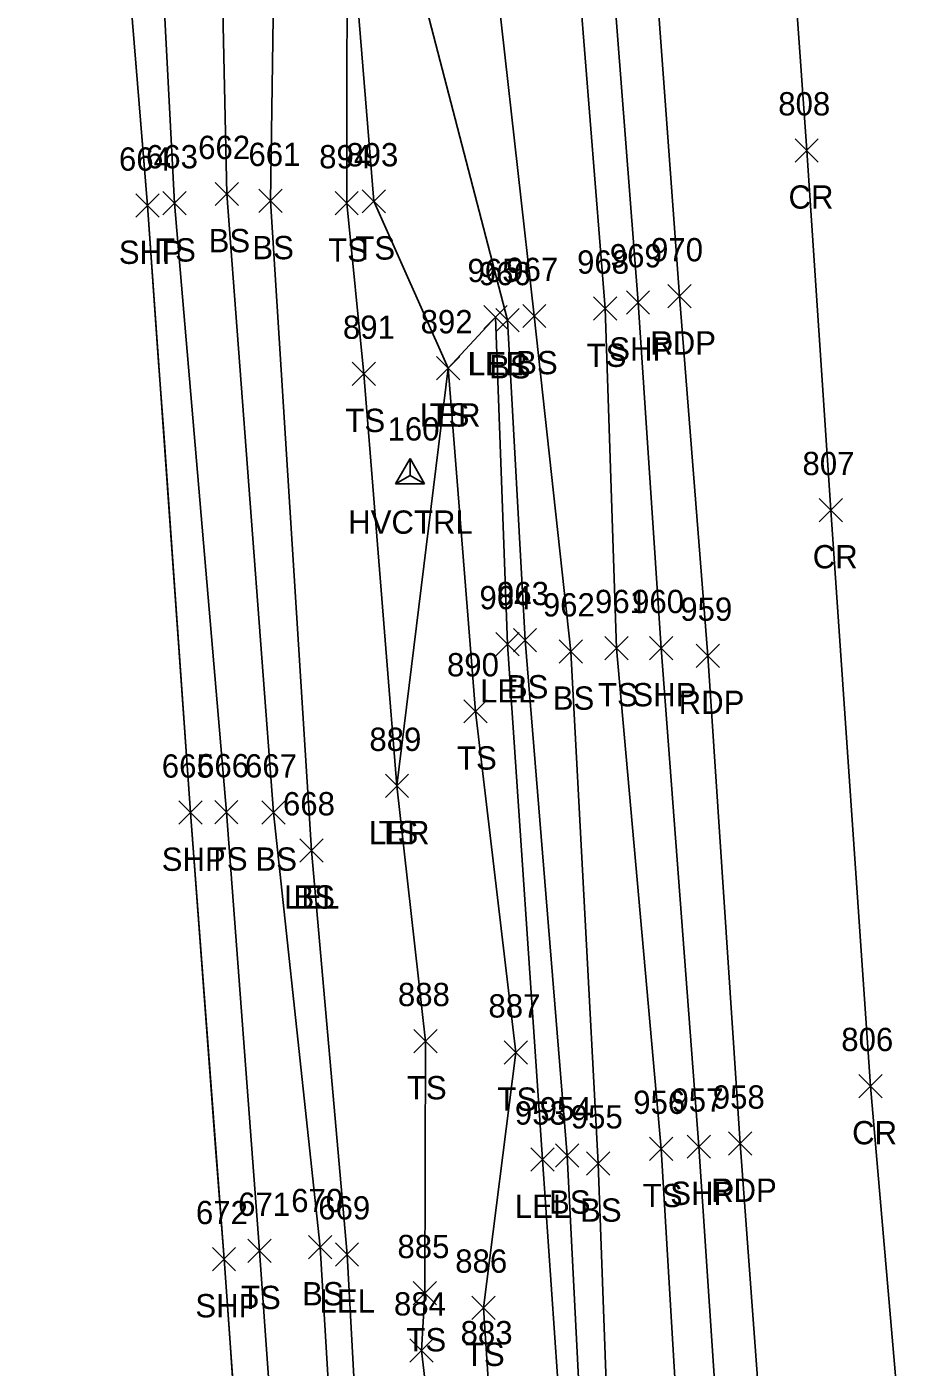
# Model space of a CAD drawing. Extents: x 1650221 to 1650634, y 244606 to 249996.
# Drawn here: x 1650345.8 to 1650421.8, y 245461.1 to 245576.1 of the extents above; entities that cross this region are included whole.
import ezdxf

# ---------------------------------------------------------------- set-up
doc = ezdxf.new("R2010")
doc.units = 0
for name, color, linetype in [('C_A', 7, 'Continuous'), ('C_I', 7, 'Continuous'), ('CPSM', 7, 'Continuous'), ('L_A', 7, 'Continuous'), ('L_I', 7, 'Continuous'), ('L_TIC', 7, 'Continuous'), ('LARO', 7, 'Continuous'), ('LELB', 7, 'Continuous'), ('LSOGP', 7, 'Continuous'), ('P_A', 7, 'Continuous'), ('P_I', 7, 'Continuous'), ('P_TIC', 7, 'Continuous'), ('PET', 7, 'Continuous'), ('PRC', 7, 'Continuous'), ('PSP', 7, 'Continuous')]:
    doc.layers.add(name, color=color, linetype=linetype)

msp = doc.modelspace()

# ---------------------------------------------------------------- linework, layer by layer
at = {"layer": 'CPSM'}
for p, q in [((1650377.43, 245536.88), (1650378.68, 245539.05)), ((1650379.93, 245536.88), (1650378.68, 245539.05)), ((1650378.68, 245537.6), (1650378.68, 245539.05)), ((1650377.43, 245536.88), (1650378.68, 245537.6)), ((1650378.68, 245537.6), (1650378.68, 245537.6)), ((1650378.68, 245537.6), (1650379.93, 245536.88)), ((1650377.43, 245536.88), (1650379.93, 245536.88))]:
    msp.add_line(p, q, dxfattribs=at)
at = {"layer": 'L_TIC'}
for points in [[(1650361.95, 245560.76), (1650363.95, 245562.76)], [(1650363.95, 245560.76), (1650361.95, 245562.76)], [(1650357.47, 245559.96), (1650359.47, 245561.96)], [(1650359.47, 245559.96), (1650357.47, 245561.96)], [(1650365.7, 245560.16), (1650367.7, 245562.16)], [(1650367.7, 245560.16), (1650365.7, 245562.16)], [(1650372.24, 245559.96), (1650374.24, 245561.96)], [(1650374.24, 245559.96), (1650372.24, 245561.96)], [(1650374.57, 245560.13), (1650376.57, 245562.13)], [(1650376.57, 245560.13), (1650374.57, 245562.13)], [(1650385.02, 245550.2), (1650387.02, 245552.2)], [(1650387.02, 245550.2), (1650385.02, 245552.2)], [(1650385.02, 245550.2), (1650387.02, 245552.2)], [(1650387.02, 245550.2), (1650385.02, 245552.2)], [(1650386.04, 245549.93), (1650388.04, 245551.93)], [(1650388.04, 245549.93), (1650386.04, 245551.93)], [(1650388.35, 245550.29), (1650390.35, 245552.29)], [(1650390.35, 245550.29), (1650388.35, 245552.29)], [(1650394.43, 245550.92), (1650396.43, 245552.92)], [(1650396.43, 245550.92), (1650394.43, 245552.92)], [(1650373.72, 245545.33), (1650375.72, 245547.33)], [(1650375.72, 245545.33), (1650373.72, 245547.33)], [(1650380.95, 245545.8), (1650382.95, 245547.8)], [(1650382.95, 245545.8), (1650380.95, 245547.8)], [(1650380.95, 245545.8), (1650382.95, 245547.8)], [(1650382.95, 245545.8), (1650380.95, 245547.8)], [(1650387.55, 245522.47), (1650389.55, 245524.47)], [(1650389.55, 245522.47), (1650387.55, 245524.47)], [(1650386.05, 245522.12), (1650388.05, 245524.12)], [(1650388.05, 245522.12), (1650386.05, 245524.12)], [(1650391.49, 245521.5), (1650393.49, 245523.5)], [(1650393.49, 245521.5), (1650391.49, 245523.5)], [(1650395.41, 245521.79), (1650397.41, 245523.79)], [(1650397.41, 245521.79), (1650395.41, 245523.79)], [(1650383.3, 245516.36), (1650385.3, 245518.36)], [(1650385.3, 245516.36), (1650383.3, 245518.36)], [(1650376.56, 245509.96), (1650378.56, 245511.96)], [(1650378.56, 245509.96), (1650376.56, 245511.96)], [(1650376.56, 245509.96), (1650378.56, 245511.96)], [(1650378.56, 245509.96), (1650376.56, 245511.96)], [(1650361.91, 245507.7), (1650363.91, 245509.7)], [(1650363.91, 245507.7), (1650361.91, 245509.7)], [(1650365.97, 245507.68), (1650367.97, 245509.68)], [(1650367.97, 245507.68), (1650365.97, 245509.68)], [(1650369.23, 245504.43), (1650371.23, 245506.43)], [(1650371.23, 245504.43), (1650369.23, 245506.43)], [(1650369.23, 245504.43), (1650371.23, 245506.43)], [(1650371.23, 245504.43), (1650369.23, 245506.43)], [(1650379, 245488.06), (1650381, 245490.06)], [(1650381, 245488.06), (1650379, 245490.06)], [(1650386.77, 245487.08), (1650388.77, 245489.08)], [(1650388.77, 245487.08), (1650386.77, 245489.08)], [(1650399.25, 245478.81), (1650401.25, 245480.81)], [(1650401.25, 245478.81), (1650399.25, 245480.81)], [(1650389.04, 245477.89), (1650391.04, 245479.89)], [(1650391.04, 245477.89), (1650389.04, 245479.89)], [(1650391.17, 245478.25), (1650393.17, 245480.25)], [(1650393.17, 245478.25), (1650391.17, 245480.25)], [(1650393.84, 245477.56), (1650395.84, 245479.56)], [(1650395.84, 245477.56), (1650393.84, 245479.56)], [(1650364.76, 245470.06), (1650366.76, 245472.06)], [(1650366.76, 245470.06), (1650364.76, 245472.06)], [(1650369.97, 245470.38), (1650371.97, 245472.38)], [(1650371.97, 245470.38), (1650369.97, 245472.38)], [(1650372.27, 245469.75), (1650374.27, 245471.75)], [(1650374.27, 245469.75), (1650372.27, 245471.75)], [(1650378.96, 245466.43), (1650380.96, 245468.43)], [(1650380.96, 245466.43), (1650378.96, 245468.43)], [(1650383.98, 245465.18), (1650385.98, 245467.18)], [(1650385.98, 245465.18), (1650383.98, 245467.18)], [(1650378.67, 245461.51), (1650380.67, 245463.51)], [(1650380.67, 245461.51), (1650378.67, 245463.51)]]:
    msp.add_lwpolyline(points, dxfattribs=at)
at = {"layer": 'LARO'}
for points in [[(1650377.56, 245510.96), (1650381.95, 245546.8), (1650386.02, 245551.2)], [(1650421.38, 244936.36), (1650423.35, 244936.27), (1650425.89, 244936.22), (1650434.3, 244938.37), (1650430.48, 244972), (1650427.02, 245018.52), (1650423.68, 245067.08), (1650420.77, 245123.48), (1650416.16, 245170.75), (1650416.29, 245170.75), (1650411.97, 245219.01), (1650407.36, 245272.17), (1650403.92, 245328.57), (1650398.22, 245379.76), (1650393.14, 245434.28), (1650390.04, 245478.89), (1650387.05, 245523.12), (1650386.02, 245551.2)], [(1650370.23, 245505.43), (1650373.27, 245470.75), (1650376.08, 245419.34), (1650380.61, 245367.82), (1650383.54, 245316.3), (1650388.29, 245270.51), (1650390.54, 245221.61), (1650394.38, 245168.62), (1650397.75, 245118.3), (1650404.08, 245063.51), (1650406.12, 245018.23), (1650409.93, 244966.8), (1650411.89, 244938.28)]]:
    msp.add_lwpolyline(points, dxfattribs=at)
at = {"layer": 'LELB'}
for points in [[(1650349.13, 245703.09), (1650351.39, 245660.59), (1650355.99, 245608.05), (1650358.47, 245560.96), (1650362.91, 245508.7), (1650365.76, 245471.06), (1650369.41, 245419.53), (1650373.04, 245367.18), (1650376.89, 245316.29), (1650379.01, 245269.77), (1650383.48, 245220.96), (1650387.1, 245168.26), (1650390.97, 245118.17), (1650394.99, 245063.19), (1650398.03, 245017.1), (1650401.94, 244967.25), (1650403.81, 244936.86), (1650407.34, 244889.23), (1650410.84, 244834.73), (1650414.52, 244785.95), (1650419.34, 244732.83), (1650422.93, 244682.99), (1650426.36, 244632.18), (1650427.51, 244611.7)], [(1650355.71, 245703.22), (1650358.45, 245660.47), (1650361.92, 245609.02), (1650362.95, 245561.76), (1650366.97, 245508.68), (1650370.97, 245471.38), (1650374.07, 245419.38), (1650376.64, 245367.03), (1650382.18, 245316.08), (1650385.68, 245270.43), (1650388.77, 245221.07), (1650390.77, 245168.69), (1650394.69, 245118), (1650401.29, 245063.19), (1650403.89, 245017.69), (1650406.99, 244966.96), (1650408.31, 244937.61), (1650413.12, 244889.16), (1650416.09, 244835.73), (1650420.51, 244786.1), (1650423.8, 244733.3), (1650426.51, 244682.57), (1650434.12, 244632.73), (1650437.01, 244612.78)], [(1650458.26, 244631.23), (1650456.79, 244671.65), (1650452.78, 244720.4), (1650448.37, 244766.08), (1650444.9, 244801.26), (1650441.62, 244837.94), (1650439.87, 244879.23), (1650437.68, 244923.9), (1650433.87, 244972.21), (1650429.49, 245017.89), (1650426.15, 245066.7), (1650422.69, 245123.12), (1650419.86, 245170.84), (1650416.52, 245219.13), (1650411.95, 245271.56), (1650407.71, 245328.35), (1650401.82, 245379.92), (1650396.45, 245433.97), (1650394.84, 245478.56), (1650392.49, 245522.5), (1650389.35, 245551.29), (1650385.12, 245588.75), (1650380.77, 245632.36), (1650373.15, 245685.41)], [(1650462.3, 244631.92), (1650459.1, 244671.43), (1650455.6, 244720.68), (1650451.8, 244765.92), (1650449.21, 244801.88), (1650446.61, 244838.72), (1650443.38, 244880.99), (1650440.04, 244922.8), (1650437.91, 244972.67), (1650433.82, 245018.12), (1650431.01, 245067.65), (1650425.84, 245123.86), (1650424.05, 245171.63), (1650419.6, 245218.92), (1650416.04, 245272.16), (1650411.76, 245328.09), (1650406.63, 245381.03), (1650402.95, 245434.27), (1650400.25, 245479.81), (1650396.41, 245522.79), (1650395.43, 245551.92), (1650392.44, 245589.61), (1650388.27, 245633.5), (1650384.04, 245685.26)], [(1650372.7, 245599.06), (1650367.15, 245592.64), (1650366.7, 245561.16), (1650370.23, 245505.43)], [(1650417.42, 245170.71), (1650414.29, 245218.92), (1650409.59, 245271.3), (1650405.4, 245327.96), (1650399.15, 245380.06), (1650394.45, 245434.24), (1650392.17, 245479.25), (1650388.55, 245523.47), (1650387.04, 245550.93), (1650374.54, 245599.04)], [(1650411.56, 245100.31), (1650410.98, 245134.62), (1650407.62, 245167.58), (1650401.15, 245195.95), (1650400.96, 245232.6), (1650396.91, 245255.72), (1650396.39, 245280.59), (1650392.18, 245317.33), (1650390.56, 245355.55), (1650386.02, 245389.39), (1650383.37, 245430.51), (1650379.67, 245462.51), (1650379.96, 245467.43), (1650380, 245489.06), (1650377.56, 245510.96), (1650374.72, 245546.33), (1650373.24, 245560.96), (1650373.27, 245589.26)], [(1650417.99, 245100.65), (1650416.66, 245133.49), (1650414.16, 245167.69), (1650410.2, 245197), (1650406.67, 245233.63), (1650402.8, 245260.5), (1650403.69, 245281.19), (1650397.99, 245316.2), (1650398.84, 245356.67), (1650390.42, 245389.46), (1650390.16, 245432.43), (1650385.39, 245460.04), (1650384.98, 245466.18), (1650387.77, 245488.08), (1650384.3, 245517.36), (1650381.95, 245546.8), (1650375.57, 245561.13), (1650373.27, 245589.26)]]:
    msp.add_lwpolyline(points, dxfattribs=at)
at = {"layer": 'LSOGP'}
msp.add_lwpolyline([(1650354.68, 245578.58), (1650355.17, 245572.64), (1650355.66, 245566.7), (1650356.14, 245560.76), (1650356.6, 245554.25), (1650357.06, 245547.74), (1650357.53, 245541.23), (1650357.99, 245534.71), (1650358.45, 245528.2), (1650358.91, 245521.69), (1650359.37, 245515.18), (1650359.83, 245508.67), (1650360.55, 245499.09), (1650361.27, 245489.51), (1650361.99, 245479.93), (1650362.71, 245470.35), (1650363.17, 245464), (1650363.62, 245457.65)], dxfattribs=at)
at = {"layer": 'P_TIC'}
for points in [[(1650411.73, 245564.5), (1650413.73, 245566.5)], [(1650413.73, 245564.5), (1650411.73, 245566.5)], [(1650355.14, 245559.76), (1650357.14, 245561.76)], [(1650357.14, 245559.76), (1650355.14, 245561.76)], [(1650397.25, 245551.46), (1650399.25, 245553.46)], [(1650399.25, 245551.46), (1650397.25, 245553.46)], [(1650400.81, 245551.98), (1650402.81, 245553.98)], [(1650402.81, 245551.98), (1650400.81, 245553.98)], [(1650413.81, 245533.63), (1650415.81, 245535.63)], [(1650415.81, 245533.63), (1650413.81, 245535.63)], [(1650399.24, 245521.79), (1650401.24, 245523.79)], [(1650401.24, 245521.79), (1650399.24, 245523.79)], [(1650403.25, 245521.13), (1650405.25, 245523.13)], [(1650405.25, 245521.13), (1650403.25, 245523.13)], [(1650358.83, 245507.67), (1650360.83, 245509.67)], [(1650360.83, 245507.67), (1650358.83, 245509.67)], [(1650417.2, 245484.2), (1650419.2, 245486.2)], [(1650419.2, 245484.2), (1650417.2, 245486.2)], [(1650402.48, 245479), (1650404.48, 245481)], [(1650404.48, 245479), (1650402.48, 245481)], [(1650406.03, 245479.26), (1650408.03, 245481.26)], [(1650408.03, 245479.26), (1650406.03, 245481.26)], [(1650361.71, 245469.35), (1650363.71, 245471.35)], [(1650363.71, 245469.35), (1650361.71, 245471.35)]]:
    msp.add_lwpolyline(points, dxfattribs=at)
at = {"layer": 'PET'}
msp.add_lwpolyline([(1650468.61, 244633.66), (1650465.16, 244679.18), (1650461.18, 244730.39), (1650457.78, 244777.29), (1650455.76, 244806.01), (1650453.3, 244838.79), (1650450.33, 244880.04), (1650447.22, 244922.32), (1650443.48, 244972.73), (1650440.49, 245018.18), (1650436.73, 245069.12), (1650432.63, 245123.79), (1650429.44, 245172.68), (1650426.2, 245218.76), (1650422.12, 245272.82), (1650418.28, 245328.28), (1650414.28, 245381.59), (1650410.42, 245434.18), (1650407.03, 245480.26), (1650404.25, 245522.13), (1650401.81, 245552.98), (1650399.16, 245589.27), (1650395.97, 245634.45), (1650392.36, 245685.55)], dxfattribs=at)
at = {"layer": 'PRC'}
msp.add_lwpolyline([(1650447.57, 245085.81), (1650443.28, 245144.22), (1650439.84, 245189.25), (1650436.21, 245244.62), (1650432.57, 245294.06), (1650428.87, 245344.44), (1650424.91, 245397.45), (1650422.06, 245440.46), (1650418.2, 245485.2), (1650414.81, 245534.63), (1650412.73, 245565.5), (1650409.49, 245611.37), (1650407.05, 245649.82), (1650403.01, 245697.04)], dxfattribs=at)
at = {"layer": 'PSP'}
for points in [[(1650345.78, 245703.18), (1650348.63, 245659.65), (1650352.24, 245608.27), (1650356.14, 245560.76), (1650359.83, 245508.67), (1650362.71, 245470.35), (1650366.37, 245419.55), (1650370.09, 245366.17), (1650373.73, 245316.16), (1650376.75, 245269.64), (1650380.21, 245220.67), (1650384.07, 245168.16), (1650387.54, 245117.86), (1650391.85, 245063.26), (1650394.9, 245017.42), (1650398.56, 244967.17), (1650400.8, 244936.49), (1650404.42, 244889.02), (1650408.47, 244833.97), (1650411.77, 244786.13), (1650415.79, 244732.16), (1650419.27, 244682.87), (1650423.02, 244632.43), (1650424.78, 244611.26)], [(1650464.84, 244632.07), (1650461.81, 244671.31), (1650457.94, 244720.75), (1650454.77, 244765.54), (1650451.99, 244802.46), (1650449.34, 244838.71), (1650446.5, 244879.72), (1650443.46, 244922.98), (1650439.98, 244973.19), (1650436.37, 245018.02), (1650433.26, 245068.28), (1650429.09, 245123.84), (1650425.59, 245171.99), (1650422.33, 245218.99), (1650418.38, 245272.19), (1650414.3, 245328), (1650410.4, 245381.3), (1650406.52, 245434.23), (1650403.48, 245480), (1650400.24, 245522.79), (1650398.25, 245552.46), (1650395.41, 245589.43), (1650392.23, 245633.8), (1650388.44, 245685.1)]]:
    msp.add_lwpolyline(points, dxfattribs=at)

# ---------------------------------------------------------------- texts
at = {"layer": 'C_A'}
msp.add_text('HVCTRL', height=2, dxfattribs=at).set_placement((1650373.37, 245532.6))
at = {"layer": 'C_I'}
msp.add_text('160', height=2, dxfattribs=at).set_placement((1650376.75, 245540.6))
at = {"layer": 'L_A'}
for s, p in [('TS', (1650356.88, 245555.96)), ('BS', (1650361.39, 245556.76)), ('BS', (1650365.14, 245556.16)), ('TS', (1650371.65, 245555.96)), ('TS', (1650373.98, 245556.13)), ('TS', (1650393.84, 245546.92)), ('LER', (1650383.6, 245546.2)), ('LEL', (1650383.66, 245546.2)), ('BS', (1650385.48, 245545.93)), ('BS', (1650387.79, 245546.29)), ('TS', (1650373.13, 245541.33)), ('LER', (1650379.53, 245541.8)), ('TS', (1650380.36, 245541.8)), ('LEL', (1650384.69, 245518.12)), ('BS', (1650386.99, 245518.47)), ('TS', (1650394.82, 245517.79)), ('BS', (1650390.93, 245517.5)), ('TS', (1650382.71, 245512.36)), ('LER', (1650375.15, 245505.96)), ('TS', (1650375.97, 245505.96)), ('TS', (1650361.32, 245503.7)), ('BS', (1650365.41, 245503.68)), ('LEL', (1650367.86, 245500.43)), ('BS', (1650368.67, 245500.43)), ('TS', (1650378.41, 245484.06)), ('TS', (1650386.18, 245483.08)), ('BS', (1650390.61, 245474.25)), ('TS', (1650398.66, 245474.81)), ('LEL', (1650387.68, 245473.89)), ('BS', (1650393.28, 245473.56)), ('TS', (1650364.17, 245466.06)), ('BS', (1650369.41, 245466.38)), ('LEL', (1650370.91, 245465.75)), ('TS', (1650378.37, 245462.43)), ('TS', (1650383.39, 245461.18))]:
    msp.add_text(s, height=2, dxfattribs=at).set_placement(p)
at = {"layer": 'L_I'}
for s, p in [('663', (1650356.01, 245563.96)), ('662', (1650360.49, 245564.76)), ('661', (1650364.81, 245564.16)), ('894', (1650370.88, 245563.96)), ('893', (1650373.21, 245564.13)), ('968', (1650393.02, 245554.92)), ('965', (1650383.61, 245554.2)), ('965', (1650383.61, 245554.2)), ('966', (1650384.58, 245553.93)), ('967', (1650386.94, 245554.29)), ('891', (1650372.92, 245549.33)), ('892', (1650379.59, 245549.8)), ('892', (1650379.59, 245549.8)), ('964', (1650384.64, 245526.12)), ('963', (1650386.14, 245526.47)), ('961', (1650394.56, 245525.79)), ('962', (1650390.08, 245525.5)), ('890', (1650381.85, 245520.36)), ('889', (1650375.19, 245513.96)), ('889', (1650375.19, 245513.96)), ('666', (1650360.4, 245511.7)), ('667', (1650364.51, 245511.68)), ('668', (1650367.77, 245508.43)), ('668', (1650367.77, 245508.43)), ('888', (1650377.64, 245492.06)), ('887', (1650385.41, 245491.08)), ('954', (1650389.81, 245482.25)), ('956', (1650397.84, 245482.81)), ('953', (1650387.68, 245481.89)), ('955', (1650392.48, 245481.56)), ('671', (1650363.92, 245474.06)), ('670', (1650368.48, 245474.38)), ('669', (1650370.8, 245473.75)), ('885', (1650377.6, 245470.43)), ('886', (1650382.56, 245469.18)), ('884', (1650377.3, 245465.51)), ('883', (1650383.02, 245463.04))]:
    msp.add_text(s, height=2, dxfattribs=at).set_placement(p)
at = {"layer": 'P_A'}
for s, p in [('CR', (1650411.17, 245560.5)), ('SHP', (1650353.68, 245555.76)), ('RDP', (1650399.3, 245547.98)), ('SHP', (1650395.78, 245547.46)), ('CR', (1650413.25, 245529.63)), ('SHP', (1650397.77, 245517.79)), ('RDP', (1650401.74, 245517.13)), ('SHP', (1650357.36, 245503.67)), ('CR', (1650416.63, 245480.2)), ('RDP', (1650404.52, 245475.26)), ('SHP', (1650401.02, 245475)), ('SHP', (1650360.25, 245465.35))]:
    msp.add_text(s, height=2, dxfattribs=at).set_placement(p)
at = {"layer": 'P_I'}
for s, p in [('808', (1650410.29, 245568.5)), ('664', (1650353.69, 245563.76)), ('970', (1650399.37, 245555.98)), ('969', (1650395.83, 245555.46)), ('807', (1650412.37, 245537.63)), ('960', (1650397.74, 245525.79)), ('959', (1650401.88, 245525.13)), ('665', (1650357.37, 245511.67)), ('806', (1650415.7, 245488.2)), ('958', (1650404.67, 245483.26)), ('957', (1650401.12, 245483)), ('672', (1650360.3, 245473.35))]:
    msp.add_text(s, height=2, dxfattribs=at).set_placement(p)

doc.saveas('drawing.dxf')
